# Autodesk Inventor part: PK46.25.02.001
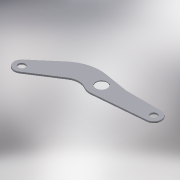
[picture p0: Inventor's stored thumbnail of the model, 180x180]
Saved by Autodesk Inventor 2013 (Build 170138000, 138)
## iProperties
Created: 2005-04
Part Number: PK46.25.02.001
Material: Steel, Mild
Document SubType Name: Modeling
Designer: salex
Manufacturer: Standard
Standards Organization: Custom
Density: 7.86 g/cm^3
Mass: 59061.7 g
Surface Area: 8472.26 cm^2
Volume: 7514.21 cm^3
Author: salex
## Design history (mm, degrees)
sketch "Эскиз1"
  geometry: L1 (0, 0)-(690, 0); L2 (690, 100)-(225, 100); L3 (225, 100)-(-92.453, 153.139); L4 (698.696, -99.621)-(13.913, -159.394); L5 (-71.528, -143.121)-(-105.59, -126.098); L6 (-695.946, -389.132)-(-303.108, -136.736); L7 (-814.936, -228.952)-(-499.681, 40.24); C1 r 75 at (0, 0); C2 r 45 at (690, 0); C3 r 45 at (-750, -305); A1 r 100 centre (690, 0) between (698.696, -99.621) and (690, 100); A2 r 100 centre (-750, -305) between (-814.936, -228.952) and (-695.946, -389.132); A3 r 200 centre (-195, -305) between (-105.59, -126.098) and (-303.108, -136.736); A4 r 160 centre (0, 0) between (-71.528, -143.121) and (13.913, -159.394); A5 r 500 centre (-175, -340) between (-92.453, 153.139) and (-499.681, 40.24)
  constraints: 14 end point, 10 point on circle, 10 tangent, 8 centre point, 3 coincident, 2 equal radius, 1 horizontal, 1 parallel, 1 other
  dimensions: "d0" = 690 distance of A1.centre A4.centre; "d1" = 90 diameter of C3; "d2" = 200 diameter of A2; "d4" = 400 diameter of A3; "d5" = 1440 horizontal distance of C3.centre L1.end; "d6" = 305 distance from line of L1 A3.centre; "d7" = 195 horizontal distance of L1.start A3.centre; "d8" = 160 radius of A4; "d9" = 150 diameter of C1; "d10" = 340 distance from line of A5.centre L1; "d11" = 175 horizontal distance of L1.start A5.centre; "d12" = 500 radius of A5; "d13" = 225 horizontal distance of L2.end L1.start; "d14" = 305 distance from line of C3.centre L1
extrude "Выдавливание1" new body sketch "Эскиз1" distance "d15" = 20; taper "d16" = 0 deg
chamfer "Фаска1" distance "d17" = 12; stored, may be unused: second distance "d18" = 2, angle "d19" = 45 deg
body "Solid1"
